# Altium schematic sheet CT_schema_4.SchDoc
size 382 x 218 mm
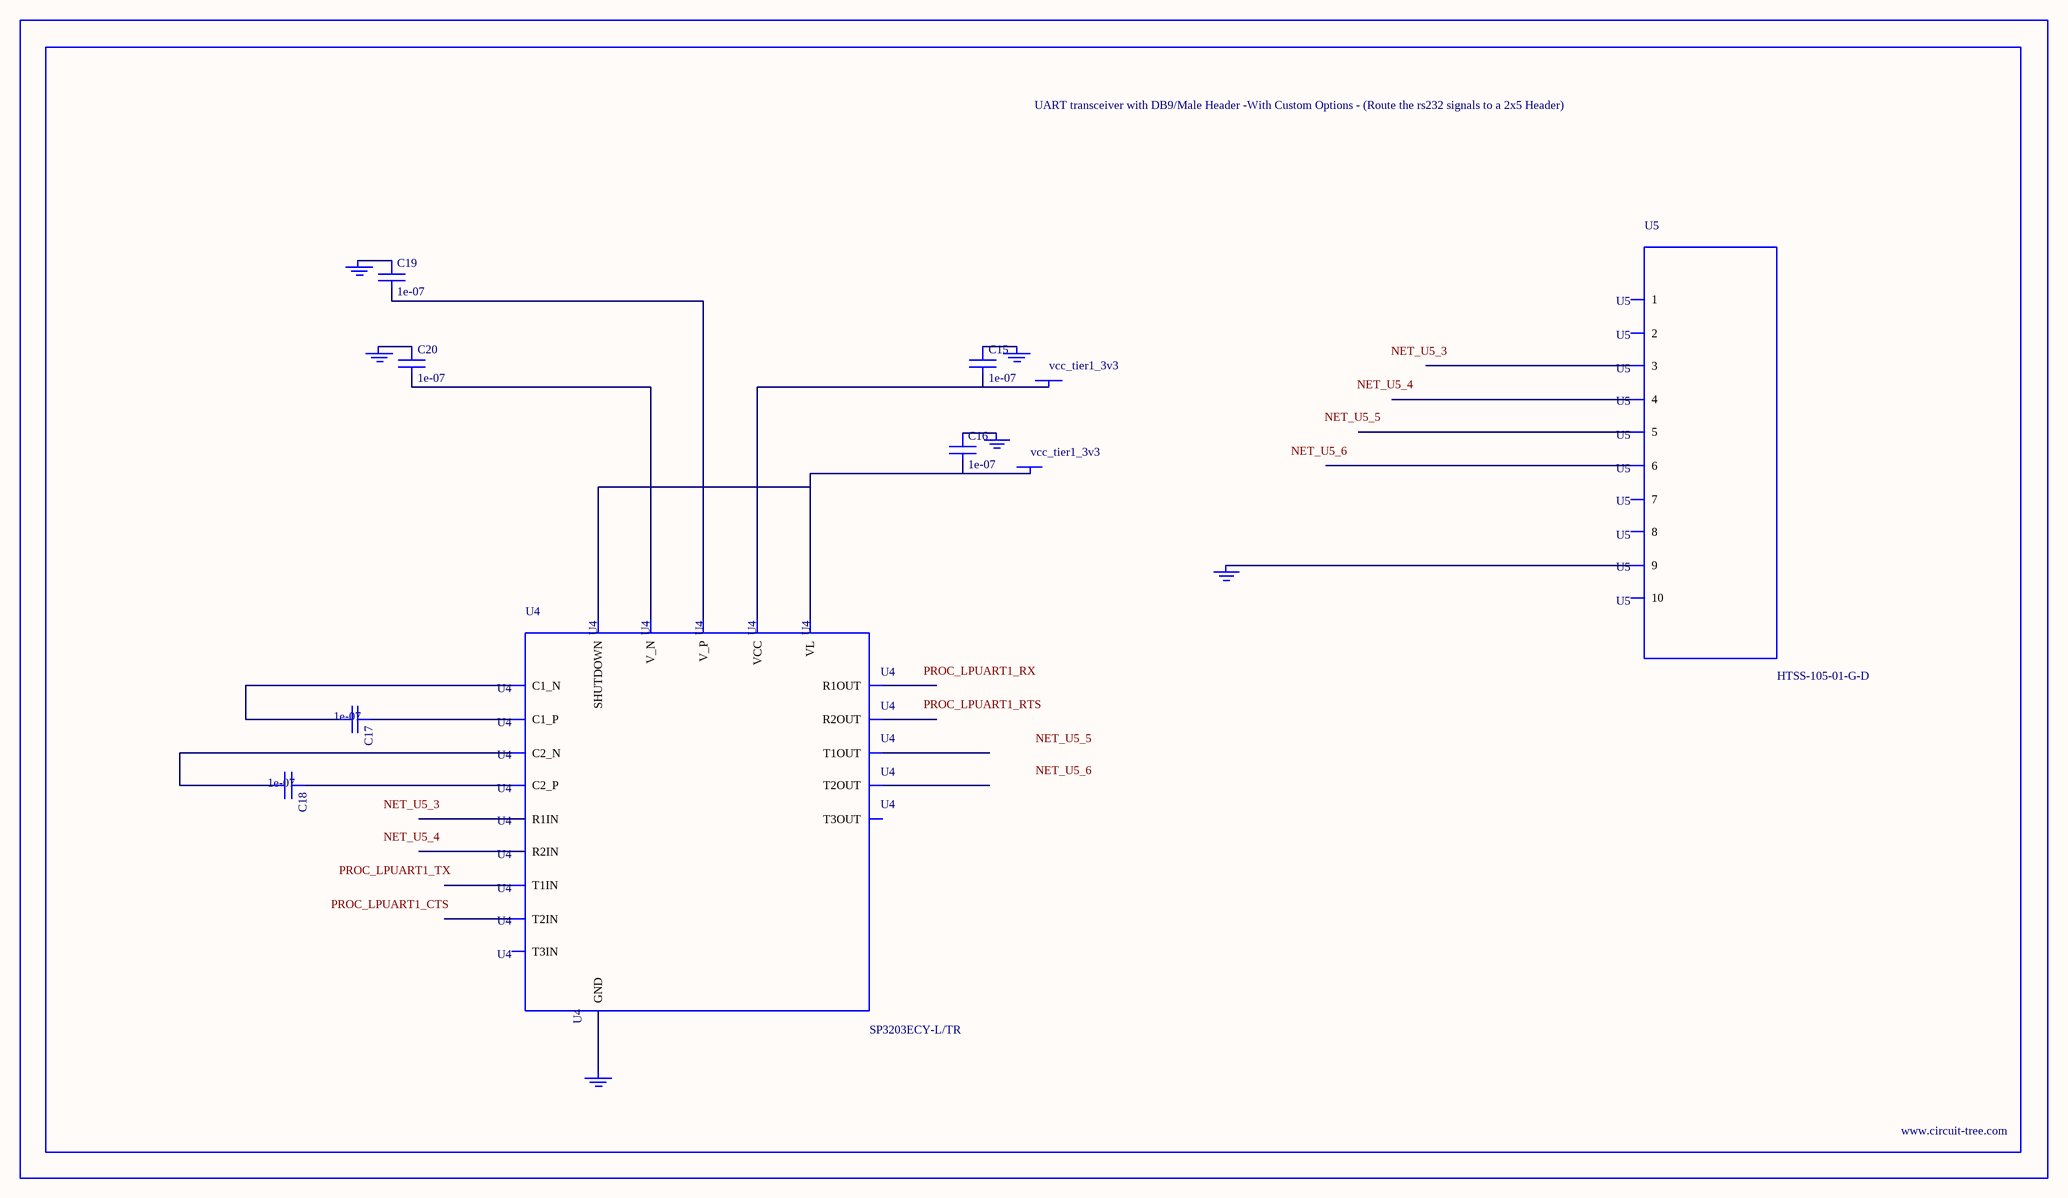
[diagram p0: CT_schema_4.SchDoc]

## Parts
BORDER3  (no value)
C15  1e-07  [C0402]
C16  1e-07  [C0402]
C17  1e-07  [C0402]
C18  1e-07  [C0402]
C19  1e-07  [C0402]
C20  1e-07  [C0402]
GND_INSTANCE_3_0  (no value)
GND_INSTANCE_3_1  (no value)
GND_INSTANCE_3_2  (no value)
GND_INSTANCE_3_3  (no value)
GND_INSTANCE_3_4  (no value)
GND_INSTANCE_3_5  (no value)
POWER_INSTANCE_3_0  vcc_tier1_3v3
POWER_INSTANCE_3_1  vcc_tier1_3v3
U4  SP3203ECY-L/TR  [TSSOP20-I]
U5  HTSS-105-01-G-D  [HTSS-105-01-G-D]

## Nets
NetC15_1: C15.1 GND_INSTANCE_3_3.0(GND)
NetC15_2: C15.2 POWER_INSTANCE_3_1.0(PWR) U4.19(VCC)
NetC16_1: C16.1 GND_INSTANCE_3_2.0(GND)
NetC16_2: C16.2 POWER_INSTANCE_3_0.0(PWR) U4.12(VL) U4.20(SHUTDOWN)
NetC17_1: C17.1 U4.1(C1_P)
NetC17_2: C17.2 U4.3(C1_N)
NetC18_1: C18.1 U4.4(C2_P)
NetC18_2: C18.2 U4.5(C2_N)
NetC19_1: C19.1 GND_INSTANCE_3_0.0(GND)
NetC19_2: C19.2 U4.2(V_P)
NetC20_1: C20.1 GND_INSTANCE_3_1.0(GND)
NetC20_2: C20.2 U4.6(V_N)
NetGND_INSTANCE_3_4_0: GND_INSTANCE_3_4.0(GND) U4.18(GND)
NetGND_INSTANCE_3_5_0: GND_INSTANCE_3_5.0(GND) U5.9

Not connected (* = marked no-connect by the designer): U4 7(T1IN) 8(T2IN) 9(T3IN) 10(R2OUT) 11(R1OUT) 13(R2IN) 14(R1IN) 15(T3OUT) 16(T2OUT) 17(T1OUT); U5 1 2 3 4 5 6 7 8 10

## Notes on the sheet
- Labels drawn without touching a wire or pin: NET_U5_3, NET_U5_4, NET_U5_5, NET_U5_6, PROC_LPUART1_CTS, PROC_LPUART1_RTS, PROC_LPUART1_RX, PROC_LPUART1_TX

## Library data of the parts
BORDER3 = BORDER_PAGE3
C15-C20 = C0402C104K3RACTU
GND_INSTANCE_3_0-GND_INSTANCE_3_5 = GND
POWER_INSTANCE_3_0 POWER_INSTANCE_3_1 = PWR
